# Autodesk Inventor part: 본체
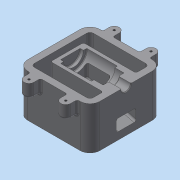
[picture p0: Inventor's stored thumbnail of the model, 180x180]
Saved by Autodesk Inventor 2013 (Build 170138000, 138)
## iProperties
Created: 2018-01
Part Number: 본체
Material: 일반
Document SubType Name: Modeling
Designer: dgall
Density: 1 g/cm^3
Author: dgall
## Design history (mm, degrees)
sketch "스케치1"
  geometry: L1 (-55, 55)-(55, 55); L2 (55, 55)-(55, -55); L3 (55, -55)-(-55, -55); L4 (-55, -55)-(-55, 55); L5 (-45, 45)-(45, 45); L6 (45, 45)-(45, -45); L7 (45, -45)-(-45, -45); L8 (-45, -45)-(-45, 45); 5 further points
  constraints: 16 end point, 4 midpoint, 3 parallel, 3 vertical, 2 horizontal, 2 horizontal alignment, 2 vertical alignment
  dimensions: "d0" = 110 distance of L1.start L1.end; "d2" = 110 distance of L1.end L2.end; "d3" = 90 distance of L5.start L5.end; "d4" = 90 distance of L5.end L6.end
extrude "돌출1" new body sketch "스케치1" stored distance "d5" = 65; taper "d6" = 0 deg
fillet "모깎기1" dims "d7" = 15
fillet "모깎기2" dims "d8" = 5
sketch "스케치2"
  geometry: L1 (40, 55)-(-40, 55) reference; L2 (-55, 40)-(-55, -40) reference; L3 (-35.5, 65)-(-35.5, 55); L4 (-20.5, 65)-(-20.5, 55); L5 (20.5, 65)-(20.5, 55); L6 (35.5, 65)-(35.5, 55); A1 r 7.5 centre (-28, 65) between (-20.5, 65) and (-35.5, 65); A2 r 7.5 centre (28, 65) between (35.5, 65) and (20.5, 65); 1 further point
  constraints: 8 end point, 4 point on circle, 4 point on line, 4 vertical, 2 centre point, 2 parallel, 2 tangent, 1 horizontal alignment
  dimensions: "d9" = 7.5 radius of A1; "d10" = 7.5 radius of A2; "d11" = 56 distance of A2.centre A1.centre; "d12" = 27 distance from line of L2 A1.centre; "d13" = 10 distance from line of L1 A1.centre
extrude "돌출2" join sketch "스케치2" distance "d14" = 20; taper "d15" = 0 deg
sketch "스케치3"
  geometry: L1 (-45, 32.5)-(-45, -32.5) reference; L2 (-45, -32.5)-(-55, -32.5) reference; L3 (-55, -32.5)-(-55, 32.5) reference; L4 (-55, 32.5)-(-45, 32.5) reference; L5 (55, -32.5)-(45, -32.5) reference; L6 (45, -32.5)-(45, 32.5) reference; L7 (45, 32.5)-(55, 32.5) reference; L8 (55, 32.5)-(55, -32.5) reference; L9 (-45, -23.936)-(35, -2.5); L10 (35, -2.5)-(35, 32.5); L11 (-45, 32.5)-(-45, -23.936); L12 (-45, 32.5)-(35, 32.5); L13 (40, -32.5)-(-40, -32.5) reference; 1 further point
  constraints: 8 end point, 1 horizontal, 1 point on line, 1 vertical
  dimensions: "d16" = 105 deg angle of L9 L1; "d17" = 30 distance from line of L13 L9.end; "d18" = 80 distance of L1.start L10.end
extrude "돌출3" join sketch "스케치3" stored distance "d19" = 50; taper "d20" = 0 deg
sketch "스케치4"
  geometry: L1 (55, -40)-(55, 40) reference; L2 (75, 0)-(-75, 0); L3 (55, 0)-(55, -7.5); L4 (55, -7.5)-(36, -7.5); L5 (36, -7.5)-(36, -16); L6 (36, -16)-(22, -16); L7 (22, -16)-(22, -20); L8 (22, -20)-(-25, -20); L9 (-25, -20)-(-25, -15); L10 (-25, -15)-(-30, -15); L11 (-30, -15)-(-30, 0); 2 further points
  constraints: 20 end point, 4 vertical, 3 point on line, 2 midpoint, 1 coincident, 1 horizontal
  dimensions: "d21" = 150 distance of L2.start L2.end; "d22" = 19 distance of L3.end L4.end; "d23" = 14 distance of L5.end L6.end; "d24" = 47 distance of L7.end L8.end; "d25" = 5 distance of L9.end L10.end; "d26" = 15 diameter of L4 L2; "d27" = 32 diameter of L6 L2; "d28" = 40 diameter of L8 L2; "d29" = 30 diameter of L10 L2
revolve "회전1" sketch "스케치4" stored, may be unused: angle "d30" = 90 deg
sketch "스케치5"
  geometry: L1 (30, 17.5)-(30, 32.5) reference; L2 (30, 32.5)-(35, 32.5) reference; L3 (35, 32.5)-(35, -2.5) reference; L4 (35, -2.5)-(-45, -23.936) reference; L5 (-45, -23.936)-(-45, -32.5) reference; L6 (-45, -32.5)-(-55, -32.5) reference; L7 (-55, -32.5)-(-55, 25) reference; L8 (-55, 25)-(-36, 25) reference; L9 (-36, 25)-(-36, 16.5) reference; L10 (-36, 16.5)-(-22, 16.5) reference; L11 (-22, 16.5)-(-22, 12.5) reference; L12 (-22, 12.5)-(25, 12.5) reference; L13 (25, 12.5)-(25, 17.5) reference; L14 (25, 17.5)-(30, 17.5) reference; L15 (55, -32.5)-(45, -32.5) reference; L16 (45, -32.5)-(45, 32.5) reference; L17 (45, 32.5)-(55, 32.5) reference; L18 (55, 32.5)-(55, -32.5) reference; L19 (-55, -32.5)-(-55, 32.5) reference; L20 (-55, -3.439)-(-17, 6.743); L21 (-55, -21.439)-(20, -1.343); L22 (20, -1.343)-(20, 28.657); L23 (-17, 6.743)-(-17, 28.657); L24 (-55, -3.439)-(-55, -21.439); L25 (-17, 28.657)-(20, 28.657); 1 further point
  constraints: 12 end point, 2 point on line, 1 horizontal, 1 parallel
  dimensions: "d31" = 75 deg angle of L19 L20; "d32" = 5 distance between parallel lines of L4 L21; "d33" = 18 distance of L21.start L20.start; "d34" = 5 distance between parallel lines of L13 L22; "d35" = 5 distance between parallel lines of L23 L11; "d36" = 30 distance of L21.end L22.end
extrude "돌출4" cut sketch "스케치5" stored distance "d37" = 30; taper "d38" = 0 deg
fillet "모깎기3" dims "d39" = 3
fillet "모깎기4" dims "d40" = 3
sketch "스케치6"
  geometry: L1 (0, 0)-(80, 0) reference; L2 (95, -65)-(95, 0) reference; 2 further points
  constraints: 1 other
  dimensions: "d41" = 20 distance from line of L1 point (40, -20); "d42" = 55 distance from line of L2 point (40, -20)
feature "엠보싱1" sketch "스케치6" dims "d43" = 0.5, "d44" = 0
fillet "모깎기5" dims "d45" = 3
fillet "모깎기6" dims "d46" = 3
fillet "모깎기7" dims "d47" = 3
chamfer "모따기1" distance "d48" = 1; stored, may be unused: second distance "d49" = 2, angle "d50" = 45 deg
fillet "모깎기8" dims "d51" = 1
fillet "모깎기9" dims "d52" = 3
fillet "모깎기10" dims "d53" = 3
hole "구멍1" diameter "d56" = 3.242; stored, may be unused: countersink angle "d60" = 90 deg, drill point angle "d62" = 118 deg; dims "d54" = 10, "d55" = 10, "d57" = 9, "d58" = 4, "d59" = 2, "d61" = 11
node "솔리드1"
mirror "대칭1"
pattern_linear "직사각형 패턴1" dims "d65" = 56
node "절단 모서리 투영1"
node "절단 모서리 투영2"
